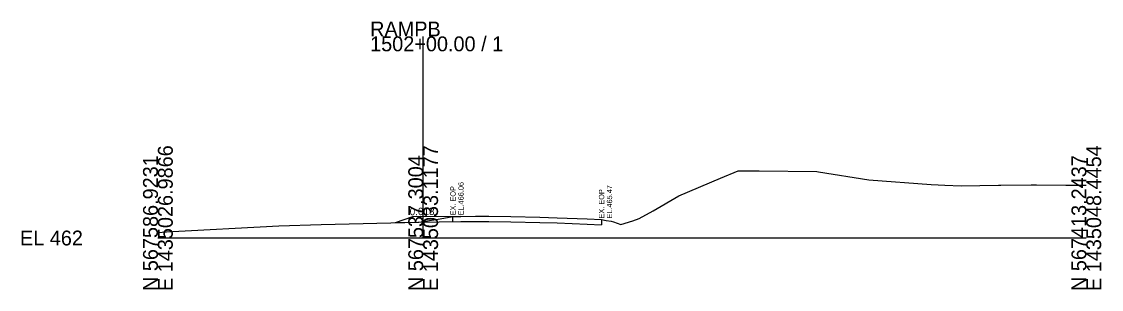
# Model space of a CAD drawing. Extents: x 1431908 to 1449087, y 567604 to 577825.
# Drawn here: x 1439484.4 to 1439688, y 573548.6 to 573599.1 of the extents above; entities that cross this region are included whole.
import ezdxf

# ---------------------------------------------------------------- set-up
doc = ezdxf.new("R2010")
doc.units = 0
for name, color, linetype in [('DESIGN - SHEET - Light Grid', 7, 'Continuous'), ('DESIGN - TYPICAL - Finished Grade and Subgrade', 7, 'Continuous'), ('SURVEY - GROUND - Existing Pavement Layer', 7, 'Continuous'), ('SURVEY - GROUND - Existing Pavement Text', 7, 'Continuous'), ('SURVEY - GROUND - Top of Ground', 7, 'Continuous')]:
    doc.layers.add(name, color=color, linetype=linetype)

msp = doc.modelspace()

# ---------------------------------------------------------------- linework, layer by layer
at = {"layer": 'DESIGN - SHEET - Light Grid'}
for p, q in [((1439560.12, 573558.33), (1439560.12, 573596.33)), ((1439510.12, 573558.33), (1439560.12, 573558.33)), ((1439560.12, 573558.33), (1439685.12, 573558.33))]:
    msp.add_line(p, q, dxfattribs=at)
at = {"layer": 'DESIGN - TYPICAL - Finished Grade and Subgrade'}
for p, q in [((1439558.12, 573562.29), (1439554.84, 573561.2)), ((1439567.21, 573562.41), (1439558.12, 573562.29))]:
    msp.add_line(p, q, dxfattribs=at)
at = {"layer": 'SURVEY - GROUND - Existing Pavement Layer'}
for p, q in [((1439555, 573561.25), (1439567.21, 573561.41)), ((1439565.74, 573561.39), (1439565.74, 573562.39)), ((1439567.21, 573561.41), (1439569.99, 573561.46)), ((1439569.99, 573561.46), (1439572.52, 573561.43)), ((1439572.52, 573561.43), (1439576.63, 573561.4)), ((1439576.63, 573561.4), (1439582.11, 573561.25)), ((1439582.11, 573561.25), (1439585.4, 573561.16)), ((1439585.4, 573561.16), (1439591.06, 573560.92)), ((1439593.74, 573561.8), (1439593.74, 573560.8)), ((1439591.06, 573560.92), (1439593.74, 573560.8))]:
    msp.add_line(p, q, dxfattribs=at)
at = {"layer": 'SURVEY - GROUND - Top of Ground'}
msp.add_lwpolyline([(1439510.12, 573559.39), (1439511.71, 573559.49), (1439532.94, 573560.6), (1439540.88, 573560.87), (1439559.28, 573561.31), (1439560.12, 573561.44), (1439563.33, 573561.96), (1439565.74, 573562.39), (1439567.21, 573562.41), (1439569.99, 573562.46), (1439572.52, 573562.43), (1439576.63, 573562.4), (1439582.11, 573562.25), (1439585.4, 573562.16), (1439591.06, 573561.92), (1439593.74, 573561.8), (1439594.61, 573561.66), (1439595.55, 573561.5), (1439595.97, 573561.36), (1439597.39, 573560.85), (1439599.62, 573561.57), (1439600.86, 573561.98), (1439603.46, 573563.47), (1439608.3, 573566.28), (1439616.17, 573569.61), (1439619.48, 573571), (1439623.43, 573570.98), (1439634.34, 573570.84), (1439634.64, 573570.8), (1439644.1, 573569.32), (1439655.86, 573568.44), (1439657.18, 573568.35), (1439658.43, 573568.3), (1439661.55, 573568.19), (1439668.57, 573568.28), (1439669.01, 573568.29), (1439674.74, 573568.37), (1439675.7, 573568.35), (1439681.27, 573568.27), (1439685.12, 573568.3)], dxfattribs=at)

# ---------------------------------------------------------------- texts
at = {"layer": 'DESIGN - SHEET - Light Grid'}
for s, p in [('RAMPB', (1439550.12, 573596.33)), ('1502+00.00 / 1', (1439550.12, 573593.53)), ('EL 462', (1439484.12, 573556.93))]:
    msp.add_text(s, height=2.8, dxfattribs=at).set_placement(p)
for s, p in [('E 1435026.9866', (1439512.92, 573548.33)), ('E 1435033.1177', (1439562.92, 573548.33)), ('E 1435048.4454', (1439687.92, 573548.33)), ('N 567586.9231', (1439510.12, 573548.33)), ('N 567537.3004', (1439560.12, 573548.33)), ('N 567413.2437', (1439685.12, 573548.33))]:
    msp.add_text(s, height=2.8, rotation=90, dxfattribs=at).set_placement(p)
at = {"layer": 'DESIGN - TYPICAL - Finished Grade and Subgrade'}
msp.add_text('0.013', height=1.4, rotation=0.7342, dxfattribs=at).set_placement((1439557.59, 573562.61))
at = {"layer": 'SURVEY - GROUND - Existing Pavement Text'}
for s, p in [('EX. EOP', (1439566.24, 573562.59)), ('EL.466.06', (1439567.74, 573562.59)), ('EX. EOP', (1439594.24, 573562)), ('EL.465.47', (1439595.74, 573562))]:
    msp.add_text(s, height=1, rotation=90, dxfattribs=at).set_placement(p)

doc.saveas('drawing.dxf')
